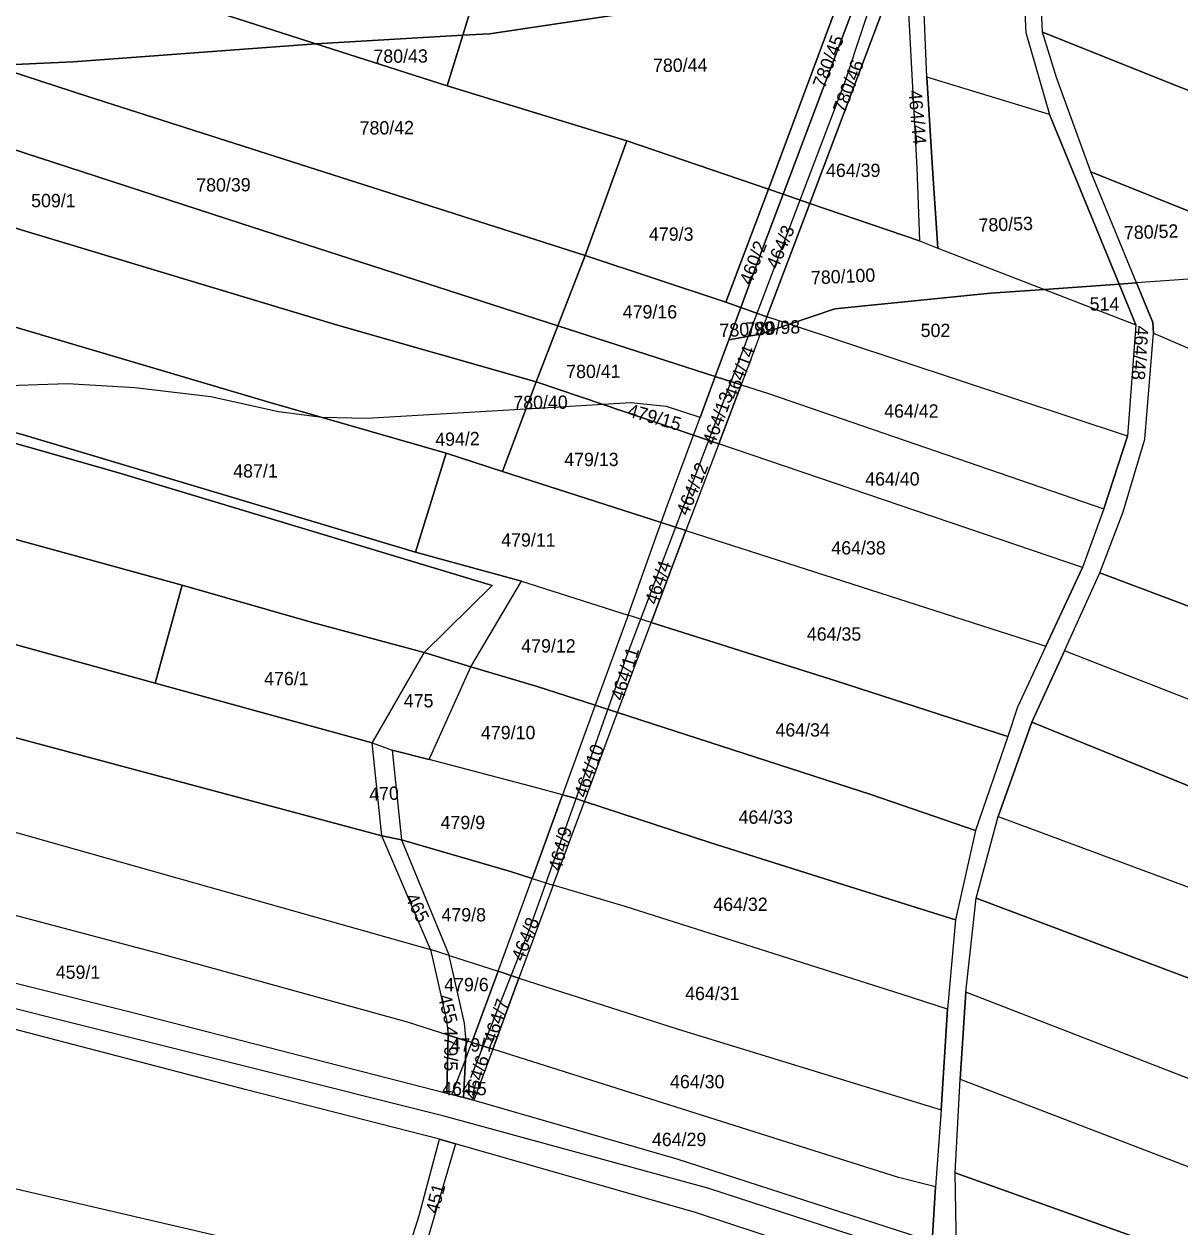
# Model space of a CAD drawing. Extents: x -629983 to -626385, y -1072828 to -1067897.
# Drawn here: x -627522.6 to -627261.8, y -1070029.7 to -1069758.5 of the extents above; entities that cross this region are included whole.
import ezdxf

# ---------------------------------------------------------------- set-up
doc = ezdxf.new("R2010")
doc.units = 0
for name, color, linetype in [('HOZ', 7, 'Continuous'), ('Parcela nároku', 7, 'Continuous'), ('Parcelní číslo', 7, 'Continuous'), ('silnice III třídy', 7, 'Continuous')]:
    doc.layers.add(name, color=color, linetype=linetype)

msp = doc.modelspace()

# ---------------------------------------------------------------- linework, layer by layer
at = {"layer": 'HOZ'}
msp.add_lwpolyline([(-627421.78, -1069996.04), (-627408.61, -1069962.8), (-627394.45, -1069923.07), (-627386.36, -1069900.38), (-627356.75, -1069822.47), (-627337.43, -1069771.65), (-627325.35, -1069735.07), (-627324.61, -1069730.09), (-627323.57, -1069723.12), (-627323.95, -1069689.95), (-627326.13, -1069623.87), (-627327.32, -1069587.7), (-627335.38, -1069526.09), (-627342.44, -1069481.41)], dxfattribs=at)
at = {"layer": 'Parcela nároku'}
for points in [[(-627738.75, -1069673.66), (-627723.89, -1069678.4), (-627667.39, -1069695.31), (-627613.74, -1069712.54), (-627456.74, -1069762.91), (-627511.5, -1069767.01), (-627529.71, -1069767.79), (-627680.28, -1069718.85), (-627692.33, -1069715.06), (-627711.43, -1069702.35), (-627733.78, -1069689.03), (-627771.83, -1069664.35)], [(-627608.26, -1069695.76), (-627421.4, -1069753.89), (-627423.59, -1069760.99), (-627456.74, -1069762.91), (-627613.74, -1069712.54)], [(-627403.61, -1069696.15), (-627328.11, -1069722.69), (-627328.03, -1069724.18), (-627333.68, -1069739.35), (-627363.45, -1069750.46), (-627386.37, -1069755.98), (-627417.61, -1069760.65), (-627423.59, -1069760.99), (-627421.4, -1069753.89), (-627415.84, -1069735.86), (-627410.1, -1069717.21), (-627407.04, -1069707.27)], [(-627281.71, -1069716.5), (-627263.41, -1069708.33), (-627251.94, -1069704.66), (-627242.51, -1069701.63), (-627230.03, -1069699.67), (-627203.9, -1069717.97), (-627230.37, -1069785.28), (-627292.84, -1069760.27), (-627294.17, -1069729.71), (-627302.54, -1069727.27)], [(-627289.72, -1069770.53), (-627292.84, -1069760.27), (-627294.17, -1069729.71), (-627302.54, -1069727.27), (-627307.84, -1069730.01), (-627297.98, -1069733.62), (-627296.6, -1069760.4), (-627291.3, -1069778.84), (-627275.58, -1069817.11), (-627271.63, -1069816.83), (-627281.95, -1069791.81)], [(-627297.98, -1069733.62), (-627296.6, -1069760.4), (-627291.3, -1069778.84), (-627318.96, -1069770.46), (-627320.38, -1069735.78), (-627309.93, -1069731.1), (-627307.84, -1069730.01)], [(-627351.35, -1069796.87), (-627329.04, -1069737.62), (-627327.72, -1069734.13), (-627324.17, -1069735.47), (-627323.83, -1069741.9), (-627345.36, -1069798.92)], [(-627320.38, -1069735.78), (-627320.49, -1069733.06), (-627321.75, -1069736.39), (-627323.83, -1069741.9), (-627321.19, -1069790.92), (-627320.62, -1069807.37), (-627316.47, -1069808.98), (-627317.68, -1069791.02), (-627318.96, -1069770.46)], [(-627333.68, -1069739.35), (-627329.04, -1069737.62), (-627351.35, -1069796.87), (-627354.68, -1069795.73)], [(-627363.45, -1069750.46), (-627333.68, -1069739.35), (-627354.68, -1069795.73), (-627386.63, -1069784.81), (-627427.11, -1069772.42), (-627423.59, -1069760.99), (-627417.61, -1069760.65), (-627386.37, -1069755.98)], [(-627345.36, -1069798.92), (-627323.83, -1069741.9), (-627321.19, -1069790.92), (-627320.62, -1069807.37)], [(-627592.68, -1069765.08), (-627571.1, -1069771.76), (-627473.63, -1069803.45), (-627402.13, -1069826.51), (-627407.04, -1069839.15), (-627451.84, -1069826.36), (-627609.39, -1069778.98), (-627630.31, -1069772.69), (-627621.4, -1069756.19)], [(-627456.74, -1069762.91), (-627423.59, -1069760.99), (-627427.11, -1069772.42)], [(-627230.37, -1069785.28), (-627189.71, -1069801.53), (-627151.32, -1069815.16), (-627224.57, -1069814.81), (-627281.95, -1069791.81), (-627289.72, -1069770.53), (-627292.84, -1069760.27)], [(-627575.06, -1069767.73), (-627549.72, -1069768.66), (-627529.71, -1069767.79), (-627508.19, -1069774.79), (-627395.97, -1069810.65), (-627402.13, -1069826.51), (-627473.63, -1069803.45), (-627571.1, -1069771.76), (-627592.68, -1069765.08)], [(-627456.74, -1069762.91), (-627427.11, -1069772.42), (-627386.63, -1069784.81), (-627395.97, -1069810.65), (-627508.19, -1069774.79), (-627529.71, -1069767.79), (-627511.5, -1069767.01)], [(-627291.3, -1069778.84), (-627318.96, -1069770.46), (-627317.68, -1069791.02), (-627316.47, -1069808.98), (-627292.4, -1069818.3), (-627275.58, -1069817.11)], [(-627646.23, -1069789.8), (-627638.29, -1069789.15), (-627625.96, -1069787.73), (-627608.8, -1069786.59), (-627609.39, -1069778.98), (-627451.84, -1069826.36), (-627407.04, -1069839.15), (-627409.36, -1069845.32), (-627445.24, -1069847.46), (-627455.34, -1069847.18), (-627467.37, -1069843.71), (-627598.56, -1069804.95), (-627636.79, -1069791.95)], [(-627386.63, -1069784.81), (-627354.68, -1069795.73), (-627364.27, -1069821.19), (-627395.97, -1069810.65)], [(-627636.79, -1069791.95), (-627598.56, -1069804.95), (-627467.37, -1069843.71), (-627455.34, -1069847.18), (-627465.14, -1069845.89), (-627480.42, -1069842.57), (-627497.61, -1069840.52), (-627512.74, -1069839.61), (-627530.54, -1069840.17), (-627554.12, -1069842.34), (-627613.09, -1069825.08), (-627699.69, -1069800.17), (-627715.85, -1069795.54), (-627646.23, -1069789.8)], [(-627281.95, -1069791.81), (-627224.57, -1069814.81), (-627241.92, -1069814.72), (-627271.63, -1069816.83)], [(-627364.27, -1069821.19), (-627354.68, -1069795.73), (-627351.35, -1069796.87), (-627355.76, -1069808.58), (-627360.86, -1069822.36)], [(-627360.86, -1069822.36), (-627355.76, -1069808.58), (-627351.35, -1069796.87), (-627345.36, -1069798.92), (-627355.03, -1069824.48)], [(-627320.62, -1069807.37), (-627316.47, -1069808.98), (-627292.4, -1069818.3), (-627304.6, -1069819.16), (-627339.72, -1069822.7), (-627349.94, -1069826.16), (-627355.03, -1069824.48), (-627345.36, -1069798.92)], [(-627402.13, -1069826.51), (-627395.97, -1069810.65), (-627364.27, -1069821.19), (-627360.86, -1069822.36), (-627363.57, -1069829.67), (-627366.65, -1069837.95)], [(-627241.92, -1069814.72), (-627271.63, -1069816.83), (-627267.94, -1069825.76), (-627267.83, -1069828.17), (-627248.42, -1069836.5), (-627155.18, -1069874.63), (-627154, -1069869.04), (-627150.4, -1069851.72), (-627148.6, -1069845.26), (-627224.57, -1069814.81)], [(-627292.4, -1069818.3), (-627271.81, -1069826.27), (-627273.65, -1069851.37), (-627349.94, -1069826.16), (-627339.72, -1069822.7), (-627304.6, -1069819.16)], [(-627275.58, -1069817.11), (-627292.4, -1069818.3), (-627271.81, -1069826.27)], [(-627360.86, -1069822.36), (-627355.03, -1069824.48), (-627356.5, -1069828.38), (-627363.57, -1069829.67)], [(-627355.03, -1069824.48), (-627356.5, -1069828.38), (-627349.94, -1069826.16)], [(-627407.04, -1069839.15), (-627402.13, -1069826.51), (-627366.65, -1069837.95), (-627370.08, -1069847.19), (-627377.66, -1069844.74), (-627385.77, -1069843.91), (-627391.95, -1069844.28)], [(-627356.5, -1069828.38), (-627360.82, -1069839.83), (-627354.65, -1069841.82), (-627279.04, -1069867.83), (-627273.65, -1069851.37), (-627349.94, -1069826.16)], [(-627366.65, -1069837.95), (-627363.57, -1069829.67), (-627356.5, -1069828.38), (-627360.82, -1069839.83)], [(-627267.83, -1069828.17), (-627248.42, -1069836.5), (-627155.18, -1069874.63), (-627159.39, -1069894.65), (-627163.63, -1069926.9), (-627217.96, -1069905.51), (-627279.93, -1069882.21), (-627274.63, -1069868.47), (-627269.77, -1069852.06)], [(-627366.65, -1069837.95), (-627360.82, -1069839.83), (-627365.85, -1069853.14), (-627371.57, -1069851.2), (-627370.08, -1069847.19)], [(-627465.14, -1069845.89), (-627480.42, -1069842.57), (-627497.61, -1069840.52), (-627512.74, -1069839.61), (-627530.54, -1069840.17), (-627554.12, -1069842.34), (-627541.91, -1069845.92), (-627522.43, -1069851.15), (-627434.26, -1069877.57), (-627427.32, -1069855.25), (-627455.34, -1069847.18)], [(-627407.04, -1069839.15), (-627391.95, -1069844.28), (-627409.36, -1069845.32)], [(-627360.82, -1069839.83), (-627354.65, -1069841.82), (-627279.04, -1069867.83), (-627283.83, -1069880.99), (-627365.85, -1069853.14)], [(-627585.1, -1069845.19), (-627617.56, -1069848.51), (-627540.57, -1069870.31), (-627486.88, -1069885.02), (-627457.8, -1069893.35), (-627432.34, -1069900.21), (-627416.95, -1069885.05), (-627469.31, -1069869.3), (-627501.47, -1069859.59), (-627542.17, -1069848.06), (-627560.21, -1069842.9)], [(-627541.91, -1069845.92), (-627554.12, -1069842.34), (-627560.21, -1069842.9), (-627542.17, -1069848.06), (-627501.47, -1069859.59), (-627469.31, -1069869.3), (-627416.95, -1069885.05), (-627432.34, -1069900.21), (-627421.81, -1069903.42), (-627410.35, -1069884.14), (-627434.26, -1069877.57), (-627522.43, -1069851.15)], [(-627445.24, -1069847.46), (-627455.34, -1069847.18), (-627427.32, -1069855.25), (-627414.64, -1069859.39), (-627409.36, -1069845.32)], [(-627391.95, -1069844.28), (-627409.36, -1069845.32), (-627414.64, -1069859.39), (-627378.84, -1069870.9), (-627377.49, -1069867.14), (-627371.57, -1069851.2)], [(-627370.08, -1069847.19), (-627377.66, -1069844.74), (-627385.77, -1069843.91), (-627391.95, -1069844.28), (-627371.57, -1069851.2)], [(-627486.88, -1069885.02), (-627540.57, -1069870.31), (-627617.56, -1069848.51), (-627624.28, -1069849.16), (-627682.41, -1069854.61), (-627601.09, -1069877.27), (-627493, -1069907.13)], [(-627378.84, -1069870.9), (-627377.49, -1069867.14), (-627371.57, -1069851.2), (-627365.85, -1069853.14), (-627373.26, -1069872.69)], [(-627730.81, -1069859.1), (-627740.39, -1069860.89), (-627741.72, -1069861.36), (-627655.72, -1069884.99), (-627548.83, -1069912.86), (-627441.85, -1069941.53), (-627444.08, -1069920.53), (-627493, -1069907.13), (-627601.09, -1069877.27), (-627682.41, -1069854.61), (-627699.35, -1069856.2)], [(-627365.85, -1069853.14), (-627373.26, -1069872.69), (-627292.09, -1069898.78), (-627283.83, -1069880.99)], [(-627427.32, -1069855.25), (-627434.26, -1069877.57), (-627410.35, -1069884.14), (-627386.33, -1069891.75), (-627378.84, -1069870.9), (-627414.64, -1069859.39)], [(-627548.83, -1069912.86), (-627655.72, -1069884.99), (-627741.72, -1069861.36), (-627748.37, -1069863.67), (-627751.23, -1069866.23), (-627753.41, -1069871.79), (-627748.47, -1069882.32), (-627659.07, -1069907.79), (-627610.96, -1069919.94), (-627531, -1069938.9), (-627430.9, -1069967.18), (-627441.85, -1069941.53)], [(-627378.84, -1069870.9), (-627373.26, -1069872.69), (-627381.11, -1069893.4), (-627386.33, -1069891.75)], [(-627373.26, -1069872.69), (-627292.09, -1069898.78), (-627298.47, -1069912.49), (-627300.7, -1069919.17), (-627339.22, -1069906.67), (-627381.11, -1069893.4)], [(-627427.28, -1069983.08), (-627426.9, -1069986.46), (-627436.08, -1069983.56), (-627491.07, -1069968.41), (-627537.37, -1069956.15), (-627582.34, -1069944.92), (-627648.68, -1069929.19), (-627737.22, -1069906.76), (-627748.47, -1069882.32), (-627659.07, -1069907.79), (-627610.96, -1069919.94), (-627531, -1069938.9), (-627430.9, -1069967.18)], [(-627410.35, -1069884.14), (-627386.33, -1069891.75), (-627393.73, -1069912.09), (-627406.84, -1069907.84), (-627421.81, -1069903.42)], [(-627217.96, -1069905.51), (-627163.63, -1069926.9), (-627163.68, -1069927.25), (-627165.64, -1069947.52), (-627287.9, -1069899.84), (-627279.93, -1069882.21)], [(-627432.34, -1069900.21), (-627457.8, -1069893.35), (-627486.88, -1069885.02), (-627493, -1069907.13), (-627444.08, -1069920.53)], [(-627386.33, -1069891.75), (-627393.73, -1069912.09), (-627388.7, -1069913.72), (-627381.11, -1069893.4)], [(-627339.22, -1069906.67), (-627300.7, -1069919.17), (-627307.94, -1069940.33), (-627331.59, -1069932.23), (-627388.7, -1069913.72), (-627381.11, -1069893.4)], [(-627421.81, -1069903.42), (-627432.34, -1069900.21), (-627444.08, -1069920.53), (-627439.54, -1069922.2), (-627431.18, -1069924.35)], [(-627287.9, -1069899.84), (-627295.23, -1069915.87), (-627242.19, -1069937.45), (-627167.17, -1069966.33), (-627167.1, -1069962.6), (-627165.64, -1069947.52)], [(-627406.84, -1069907.84), (-627393.73, -1069912.09), (-627401.09, -1069932.3), (-627407.21, -1069930.61), (-627431.18, -1069924.35), (-627421.81, -1069903.42)], [(-627393.73, -1069912.09), (-627401.09, -1069932.3), (-627398.56, -1069933), (-627396.18, -1069933.77), (-627388.7, -1069913.72)], [(-627396.18, -1069933.77), (-627388.7, -1069913.72), (-627331.59, -1069932.23), (-627307.94, -1069940.33), (-627312.46, -1069960.46), (-627336.43, -1069952.99), (-627367.62, -1069943.08)], [(-627295.23, -1069915.87), (-627302.86, -1069937.18), (-627188.97, -1069979.41), (-627168.26, -1069986.73), (-627167.38, -1069976.56), (-627167.17, -1069966.33), (-627242.19, -1069937.45)], [(-627439.54, -1069922.2), (-627437.42, -1069942.45), (-627441.85, -1069941.53), (-627444.08, -1069920.53)], [(-627401.09, -1069932.3), (-627407.21, -1069930.61), (-627431.18, -1069924.35), (-627439.54, -1069922.2), (-627437.42, -1069942.45), (-627412.83, -1069949.6), (-627407.98, -1069951.15)], [(-627398.56, -1069933), (-627401.09, -1069932.3), (-627407.98, -1069951.15), (-627403.21, -1069952.67), (-627396.18, -1069933.77)], [(-627336.43, -1069952.99), (-627312.46, -1069960.46), (-627314.28, -1069980.63), (-627324.49, -1069977.32), (-627386.98, -1069957.44), (-627403.21, -1069952.67), (-627396.18, -1069933.77), (-627367.62, -1069943.08)], [(-627302.86, -1069937.18), (-627188.97, -1069979.41), (-627168.26, -1069986.73), (-627168.99, -1069995.1), (-627170.55, -1070007.26), (-627307.82, -1069955.61)], [(-627441.85, -1069941.53), (-627437.42, -1069942.45), (-627426.7, -1069968.52), (-627430.9, -1069967.18)], [(-627412.83, -1069949.6), (-627437.42, -1069942.45), (-627426.7, -1069968.52), (-627415.66, -1069972.08), (-627407.98, -1069951.15)], [(-627537.37, -1069956.15), (-627582.34, -1069944.92), (-627585.73, -1069959.62), (-627573.05, -1069962.58), (-627497.44, -1069981.55), (-627427.24, -1069999.55), (-627426.9, -1069986.46), (-627436.08, -1069983.56), (-627491.07, -1069968.41)], [(-627415.66, -1069972.08), (-627407.98, -1069951.15), (-627403.21, -1069952.67), (-627410.94, -1069973.6)], [(-627386.98, -1069957.44), (-627403.21, -1069952.67), (-627410.94, -1069973.6), (-627375.03, -1069985.17), (-627315.74, -1070003.3), (-627314.28, -1069980.63), (-627324.49, -1069977.32)], [(-627307.82, -1069955.61), (-627170.55, -1070007.26), (-627172.55, -1070029.2), (-627252.36, -1069999.23), (-627310.13, -1069976.83)], [(-627423.25, -1069983.77), (-627426.7, -1069968.52), (-627430.9, -1069967.18), (-627427.28, -1069983.08), (-627426.9, -1069986.46), (-627422.83, -1069987.75)], [(-627426.7, -1069968.52), (-627415.66, -1069972.08), (-627421.56, -1069988.15), (-627422.83, -1069987.75), (-627423.25, -1069983.77)], [(-627415.66, -1069972.08), (-627410.94, -1069973.6), (-627416.86, -1069989.64), (-627421.56, -1069988.15)], [(-627410.94, -1069973.6), (-627375.03, -1069985.17), (-627315.74, -1070003.3), (-627316.95, -1070020.66), (-627325.29, -1070018.57), (-627416.86, -1069989.64)], [(-627310.13, -1069976.83), (-627311.45, -1069996.38), (-627177.32, -1070047.82), (-627172.55, -1070029.2), (-627252.36, -1069999.23)], [(-627422.83, -1069987.75), (-627426.9, -1069986.46), (-627427.24, -1069999.55), (-627426.04, -1069999.86), (-627423.03, -1069992.05)], [(-627423.03, -1069992.05), (-627422.21, -1069989.93), (-627421.56, -1069988.15), (-627416.86, -1069989.64), (-627421.1, -1070001.12), (-627423.42, -1070000.53)], [(-627421.56, -1069988.15), (-627422.83, -1069987.75), (-627423.03, -1069992.05), (-627422.21, -1069989.93)], [(-627316.95, -1070020.66), (-627325.29, -1070018.57), (-627416.86, -1069989.64), (-627421.1, -1070001.12), (-627375.29, -1070014.41), (-627317.71, -1070033.01)], [(-627426.04, -1069999.86), (-627423.03, -1069992.05), (-627423.42, -1070000.53)], [(-627311.45, -1069996.38), (-627177.32, -1070047.82), (-627181.66, -1070064.26), (-627312.58, -1070017.57)], [(-627438.03, -1070041.67), (-627433.43, -1070027.14), (-627428.85, -1070009.96), (-627425.23, -1070011), (-627434.5, -1070042.56)], [(-627370.91, -1070026.56), (-627425.23, -1070011), (-627434.5, -1070042.56), (-627411.76, -1070048.32), (-627353.35, -1070065.17), (-627330, -1070071.29), (-627325.33, -1070058.33), (-627320.75, -1070043.1)], [(-627312.58, -1070017.57), (-627181.66, -1070064.26), (-627184.24, -1070074.01), (-627190.99, -1070076.44), (-627231.22, -1070062.6), (-627290.43, -1070041.64), (-627312.23, -1070034.74)]]:
    msp.add_lwpolyline(points, close=True, dxfattribs=at)
for points in [[(-627312.23, -1070034.74), (-627312.58, -1070017.57), (-627311.45, -1069996.38), (-627310.13, -1069976.83), (-627307.82, -1069955.61), (-627302.86, -1069937.18), (-627295.23, -1069915.87), (-627287.9, -1069899.84), (-627279.93, -1069882.21), (-627274.63, -1069868.47), (-627269.77, -1069852.06), (-627267.83, -1069828.17), (-627267.94, -1069825.76), (-627271.63, -1069816.83), (-627275.58, -1069817.11), (-627271.81, -1069826.27), (-627273.65, -1069851.37), (-627279.04, -1069867.83), (-627283.83, -1069880.99), (-627292.09, -1069898.78), (-627298.47, -1069912.49), (-627300.7, -1069919.17), (-627307.94, -1069940.33), (-627312.46, -1069960.46), (-627314.28, -1069980.63), (-627315.74, -1070003.3), (-627316.95, -1070020.66), (-627317.71, -1070033.01)], [(-627966.68, -1069918.48), (-627860.41, -1069943.87), (-627798.46, -1069959.34), (-627761.08, -1069969.25), (-627698.9, -1069984.16), (-627525.35, -1070020.94), (-627459.67, -1070036.19), (-627438.03, -1070041.67), (-627433.43, -1070027.14), (-627428.85, -1070009.96), (-627472.67, -1069998.76), (-627548.5, -1069979.01), (-627683.65, -1069947.01), (-627730.62, -1069934.75), (-627791.94, -1069919.96), (-627822.96, -1069911.43), (-627871.54, -1069899.35), (-627908.74, -1069890.74), (-627953.38, -1069880.27)], [(-627966.68, -1069918.48), (-627860.41, -1069943.87), (-627798.46, -1069959.34), (-627761.08, -1069969.25), (-627698.9, -1069984.16), (-627525.35, -1070020.94), (-627459.67, -1070036.19), (-627438.03, -1070041.67), (-627434.5, -1070042.56), (-627411.76, -1070048.32), (-627353.35, -1070065.17), (-627330, -1070071.29), (-627336.22, -1070084.29), (-627380.22, -1070075.61), (-627408.28, -1070068.97), (-627438.24, -1070060.91), (-627479.97, -1070048.75), (-627534.6, -1070037.2), (-627642.99, -1070015.46), (-627734.04, -1069994.19), (-627855.15, -1069966.75), (-627952.86, -1069945.56)], [(-627573.05, -1069962.58), (-627497.44, -1069981.55), (-627427.24, -1069999.55), (-627426.04, -1069999.86), (-627423.42, -1070000.53), (-627421.1, -1070001.12), (-627375.29, -1070014.41), (-627317.71, -1070033.01)], [(-627320.75, -1070043.1), (-627370.91, -1070026.56), (-627425.23, -1070011), (-627428.85, -1070009.96), (-627472.67, -1069998.76), (-627548.5, -1069979.01)]]:
    msp.add_lwpolyline(points, dxfattribs=at)
at = {"layer": 'silnice III třídy'}
msp.add_lwpolyline([(-627179.13, -1070085.76), (-627198.03, -1070077.93), (-627215.91, -1070071.53), (-627241.19, -1070062.48), (-627273.72, -1070051.86), (-627313.17, -1070038.98), (-627368.35, -1070020.97), (-627428.11, -1070004.67), (-627469.26, -1069994.36), (-627510.41, -1069984.05), (-627563.5, -1069970.75), (-627602.12, -1069962.61), (-627657.83, -1069948.79), (-627708.45, -1069937.73), (-627718.05, -1069933.95), (-627728.23, -1069927.84), (-627736.09, -1069919.69), (-627744.96, -1069902.23), (-627755.43, -1069876.77)], dxfattribs=at)

# ---------------------------------------------------------------- texts
at = {"layer": 'Parcelní číslo'}
for s, rotation, p in [('780/45', 68.8695, (-627341.99, -1069773.17)), ('780/43', 0.401, (-627443.75, -1069767.24)), ('780/44', 0.401, (-627380.69, -1069769.29)), ('780/46', 68.8695, (-627337.46, -1069778.73)), ('464/44', 275.1079, (-627323.1, -1069773.53)), ('780/42', 0.401, (-627446.87, -1069783.4)), ('780/39', 0.401, (-627483.71, -1069796.28)), ('780/53', 2.12, (-627307.22, -1069805.35)), ('464/3', 67.3355, (-627352.53, -1069813.94)), ('780/52', 2.12, (-627274.42, -1069807.05)), ('460/2', 69.187, (-627358.5, -1069817.5)), ('780/100', 2.5783, (-627345, -1069817.19)), ('780/99', 2.5783, (-627365.63, -1069829.08)), ('780/98', 2.5783, (-627359.71, -1069828.76)), ('464/48', 265.8524, (-627271.89, -1069826.4)), ('464/14', 69.3279, (-627361.91, -1069843.3)), ('780/41', 0.401, (-627400.27, -1069838.33)), ('780/40', 0.401, (-627412.2, -1069845.32)), ('464/13', 69.3454, (-627366.84, -1069853.63)), ('479/15', 344.2331, (-627386.67, -1069846.91)), ('494/2', 1.3178, (-627429.79, -1069853.66)), ('464/12', 67.5806, (-627372.8, -1069869.52)), ('464/4', 70.4918, (-627379.82, -1069889.64)), ('464/11', 72.275, (-627387.48, -1069911.26)), ('464/10', 70.5525, (-627395.78, -1069933.14)), ('470', 2.3984, (-627444.65, -1069933.66)), ('464/9', 75.5835, (-627401.43, -1069949.66)), ('465', 296.565, (-627436.69, -1069955.41)), ('464/8', 68.6847, (-627409.95, -1069970.04)), ('455', 283.865, (-627429.21, -1069977.7)), ('464/7', 71.4982, (-627416.24, -1069988.47)), ('479/5', 270, (-627427.78, -1069984.56)), ('464/6', 72.6246, (-627420.59, -1070001.21)), ('451', 75.2409, (-627429.19, -1070026.93))]:
    msp.add_text(s, height=3, rotation=rotation, dxfattribs=at).set_placement(p)
for s, p in [('464/39', (-627341.68, -1069792.96)), ('509/1', (-627520.97, -1069799.78)), ('479/3', (-627381.61, -1069807.33)), ('479/16', (-627387.53, -1069824.87)), ('514', (-627282.22, -1069823.09)), ('502', (-627320.33, -1069829.05)), ('464/42', (-627328.56, -1069847.23)), ('479/13', (-627400.73, -1069858.15)), ('487/1', (-627475.39, -1069860.75)), ('464/40', (-627332.84, -1069862.55)), ('479/11', (-627414.94, -1069876.32)), ('464/38', (-627340.48, -1069878.09)), ('464/35', (-627346, -1069897.52)), ('479/12', (-627410.42, -1069900.2)), ('476/1', (-627468.41, -1069907.57)), ('475', (-627436.92, -1069912.57)), ('479/10', (-627419.5, -1069919.75)), ('464/34', (-627353.07, -1069919.15)), ('464/33', (-627361.4, -1069938.81)), ('479/9', (-627428.61, -1069940.03)), ('479/8', (-627428.41, -1069960.83)), ('464/32', (-627367.1, -1069958.47)), ('459/1', (-627515.41, -1069973.78)), ('479/6', (-627427.8, -1069976.58)), ('464/31', (-627373.45, -1069978.58)), ('479/7', (-627426.36, -1069990.18)), ('464/30', (-627376.86, -1069998.47)), ('464/5', (-627428.26, -1070000.05)), ('464/29', (-627380.94, -1070011.5))]:
    msp.add_text(s, height=3, dxfattribs=at).set_placement(p)

doc.saveas('drawing.dxf')
